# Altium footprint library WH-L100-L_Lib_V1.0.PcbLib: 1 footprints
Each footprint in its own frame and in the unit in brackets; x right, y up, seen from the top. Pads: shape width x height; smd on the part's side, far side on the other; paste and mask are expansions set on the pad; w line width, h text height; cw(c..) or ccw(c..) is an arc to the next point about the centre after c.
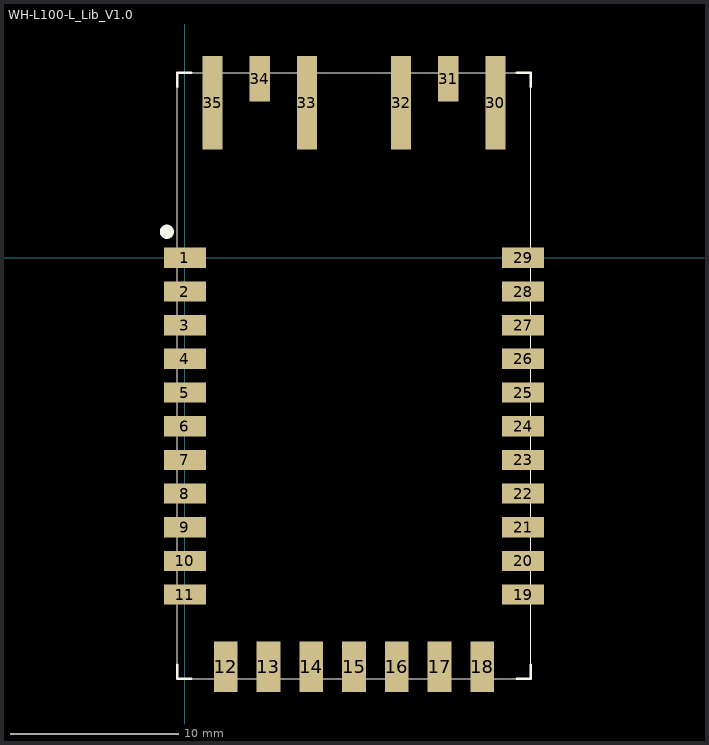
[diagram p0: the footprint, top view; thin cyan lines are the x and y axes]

## WH-L100-L_Lib_V1.0 [mm] "WH-L101封装"
pads (35):
  rect 2.5x1.2 smd: 1(0,0) 2(0,-2) 3(0,-4) 4(0,-6) 5(0,-8) 6(0,-10) 7(0,-12) 8(0,-14) 9(0,-16) 10(0,-18) 11(0,-20) 19(20.1,-20) 20(20.1,-18) 21(20.1,-16) 22(20.1,-14) 23(20.1,-12) 24(20.1,-10) 25(20.1,-8) 26(20.1,-6) 27(20.1,-4) 28(20.1,-2) 29(20.1,0)
  rect 1.4x3 smd: 12(2.43,-24.3) 13(4.97,-24.3) 14(7.51,-24.3) 15(10.05,-24.3) 16(12.59,-24.3) 17(15.13,-24.3) 18(17.67,-24.3)
  rect 1.2x5.55 smd: 30(18.45,9.225) 32(12.85,9.225) 33(7.25,9.225) 35(1.65,9.225)
  rect 1.2x2.7 smd: 31(15.65,10.65) 34(4.45,10.65)
Top Overlay:
  circle w0.762: c-1.067,1.549 r0.036
  lines w0.025: -0.45,-25 20.55,-25 20.55,11 -0.45,11 -0.45,-25
  lines w0.152: -0.45,-24.16 -0.45,-25 0.39,-25 ; -0.45,10.16 -0.45,11 0.39,11 ; 19.71,-25 20.55,-25 20.55,-24.16 ; 19.71,11 20.55,11 20.55,10.16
